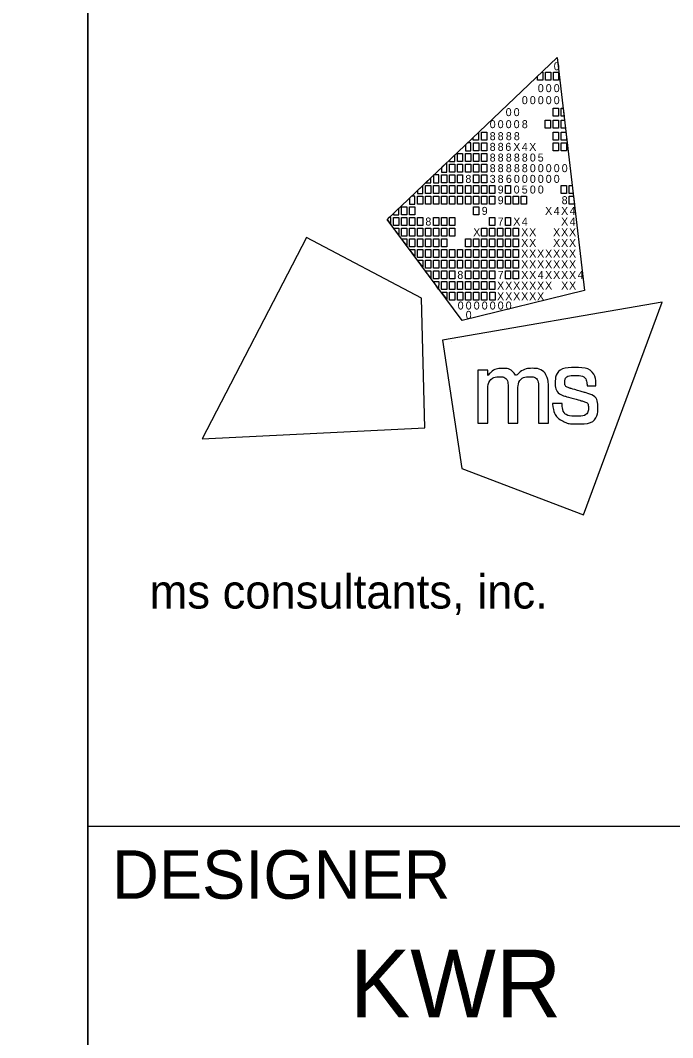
# Model space of a CAD drawing. Extents: x -0.2 to 34, y 0 to 22.
# Drawn here: x 31.86 to 33.207, y 2.063 to 4.163 of the extents above; entities that cross this region are included whole.
import ezdxf

# ---------------------------------------------------------------- set-up
doc = ezdxf.new("R2010")
doc.units = 0
for name, color, linetype in [('PV_P_Parking_Lot', 7, 'Continuous'), ('SH_Border', 7, 'Continuous'), ('SH_Data', 7, 'Continuous')]:
    doc.layers.add(name, color=color, linetype=linetype)

msp = doc.modelspace()

# ---------------------------------------------------------------- linework, layer by layer
at = {"layer": 'PV_P_Parking_Lot'}
msp.add_lwpolyline([(1.5, 21.5), (32, 21.5), (32, 0.5), (1.5, 0.5)], close=True, dxfattribs=at)
at = {"layer": 'SH_Border'}
for p, q in [((32, 0.5), (32, 21.5)), ((32, 2.5), (33.5, 2.5))]:
    msp.add_line(p, q, dxfattribs=at)
at = {"layer": 'SH_Data'}
for p, q in [((32.6175, 3.7519), (32.9688, 4.0861)), ((32.9688, 4.0861), (32.9688, 4.0861)), ((32.9688, 4.0861), (33.0253, 3.6052)), ((32.773, 3.543), (32.6175, 3.7519)), ((33.0253, 3.6052), (32.773, 3.543)), ((32.75, 3.5), (32.75, 3.5))]:
    msp.add_line(p, q, dxfattribs=at)
for points in [[(32.9279, 4.0472), (32.9369, 4.0558), (32.9389, 4.0558), (32.9389, 4.0393), (32.9279, 4.0393)], [(32.9444, 4.0558), (32.9554, 4.0558), (32.9554, 4.0393), (32.9444, 4.0393)], [(32.9609, 4.0558), (32.9719, 4.0558), (32.9719, 4.0393), (32.9609, 4.0393)], [(32.9606, 3.9815), (32.9716, 3.9815), (32.9716, 3.965), (32.9606, 3.965)], [(32.9771, 3.9815), (32.9811, 3.9815), (32.983, 3.965), (32.9771, 3.965)], [(32.9441, 3.9567), (32.9551, 3.9567), (32.9551, 3.9402), (32.9441, 3.9402)], [(32.9606, 3.9567), (32.9716, 3.9567), (32.9716, 3.9402), (32.9606, 3.9402)], [(32.9771, 3.9567), (32.984, 3.9567), (32.9859, 3.9402), (32.9771, 3.9402)], [(32.7953, 3.9211), (32.8064, 3.9316), (32.8064, 3.9154), (32.7953, 3.9154)], [(32.8123, 3.9319), (32.8233, 3.9319), (32.8233, 3.9154), (32.8123, 3.9154)], [(32.9606, 3.9319), (32.9716, 3.9319), (32.9716, 3.9154), (32.9606, 3.9154)], [(32.9771, 3.9319), (32.9869, 3.9319), (32.9881, 3.9218), (32.9881, 3.9154), (32.9771, 3.9154)], [(32.7958, 3.9099), (32.8068, 3.9099), (32.8068, 3.8934), (32.7958, 3.8934)], [(32.8123, 3.9099), (32.8233, 3.9099), (32.8233, 3.8934), (32.8123, 3.8934)], [(32.9606, 3.9099), (32.9716, 3.9099), (32.9716, 3.8934), (32.9606, 3.8934)], [(32.9771, 3.9099), (32.9881, 3.9099), (32.9881, 3.8934), (32.9771, 3.8934)], [(32.7627, 3.8879), (32.7737, 3.8879), (32.7737, 3.8714), (32.7627, 3.8714)], [(32.7793, 3.8879), (32.7903, 3.8879), (32.7903, 3.8714), (32.7793, 3.8714)], [(32.7958, 3.8879), (32.8068, 3.8879), (32.8068, 3.8714), (32.7958, 3.8714)], [(32.8123, 3.8879), (32.8233, 3.8879), (32.8233, 3.8714), (32.8123, 3.8714)], [(32.7462, 3.8659), (32.7572, 3.8659), (32.7572, 3.8494), (32.7462, 3.8494)], [(32.7627, 3.8659), (32.7737, 3.8659), (32.7737, 3.8494), (32.7627, 3.8494)], [(32.7793, 3.8659), (32.7903, 3.8659), (32.7903, 3.8494), (32.7793, 3.8494)], [(32.7958, 3.8659), (32.8068, 3.8659), (32.8068, 3.8494), (32.7958, 3.8494)], [(32.8123, 3.8659), (32.8233, 3.8659), (32.8233, 3.8494), (32.8123, 3.8494)], [(32.7297, 3.8439), (32.7407, 3.8439), (32.7407, 3.8273), (32.7297, 3.8273)], [(32.7462, 3.8439), (32.7572, 3.8439), (32.7572, 3.8273), (32.7462, 3.8273)], [(32.7627, 3.8439), (32.7737, 3.8439), (32.7737, 3.8273), (32.7627, 3.8273)], [(32.7958, 3.8439), (32.8068, 3.8439), (32.8068, 3.8273), (32.7958, 3.8273)], [(32.8123, 3.8439), (32.8233, 3.8439), (32.8233, 3.8273), (32.8123, 3.8273)], [(32.6967, 3.8218), (32.7077, 3.8218), (32.7077, 3.8053), (32.6967, 3.8053)], [(32.7132, 3.8218), (32.7242, 3.8218), (32.7242, 3.8053), (32.7132, 3.8053)], [(32.7297, 3.8218), (32.7407, 3.8218), (32.7407, 3.8053), (32.7297, 3.8053)], [(32.7462, 3.8218), (32.7572, 3.8218), (32.7572, 3.8053), (32.7462, 3.8053)], [(32.7627, 3.8218), (32.7737, 3.8218), (32.7737, 3.8053), (32.7627, 3.8053)], [(32.7793, 3.8218), (32.7903, 3.8218), (32.7903, 3.8053), (32.7793, 3.8053)], [(32.7958, 3.8218), (32.8068, 3.8218), (32.8068, 3.8053), (32.7958, 3.8053)], [(32.8123, 3.8218), (32.8233, 3.8218), (32.8233, 3.8053), (32.8123, 3.8053)], [(32.8288, 3.8218), (32.8398, 3.8218), (32.8398, 3.8053), (32.8288, 3.8053)], [(32.8618, 3.8218), (32.8728, 3.8218), (32.8728, 3.8053), (32.8618, 3.8053)], [(32.9771, 3.8218), (32.9881, 3.8218), (32.9881, 3.8053), (32.9771, 3.8053)], [(32.9935, 3.8218), (32.9998, 3.8218), (33.0018, 3.8053), (32.9935, 3.8053)], [(32.6802, 3.7998), (32.6912, 3.7998), (32.6912, 3.7833), (32.6802, 3.7833)], [(32.6967, 3.7998), (32.7077, 3.7998), (32.7077, 3.7833), (32.6967, 3.7833)], [(32.7132, 3.7998), (32.7242, 3.7998), (32.7242, 3.7833), (32.7132, 3.7833)], [(32.7297, 3.7998), (32.7407, 3.7998), (32.7407, 3.7833), (32.7297, 3.7833)], [(32.7462, 3.7998), (32.7572, 3.7998), (32.7572, 3.7833), (32.7462, 3.7833)], [(32.7627, 3.7998), (32.7737, 3.7998), (32.7737, 3.7833), (32.7627, 3.7833)], [(32.7793, 3.7998), (32.7903, 3.7998), (32.7903, 3.7833), (32.7793, 3.7833)], [(32.7958, 3.7998), (32.8068, 3.7998), (32.8068, 3.7833), (32.7958, 3.7833)], [(32.8123, 3.7998), (32.8233, 3.7998), (32.8233, 3.7833), (32.8123, 3.7833)], [(32.8288, 3.7998), (32.8398, 3.7998), (32.8398, 3.7833), (32.8288, 3.7833)], [(32.8618, 3.7998), (32.8728, 3.7998), (32.8728, 3.7833), (32.8618, 3.7833)], [(32.8783, 3.7998), (32.8893, 3.7998), (32.8893, 3.7833), (32.8783, 3.7833)], [(32.8947, 3.7998), (32.9057, 3.7998), (32.9057, 3.7833), (32.8947, 3.7833)], [(32.9935, 3.7998), (33.0024, 3.7998), (33.0044, 3.7833), (32.9935, 3.7833)], [(32.6471, 3.7778), (32.6581, 3.7778), (32.6581, 3.7613), (32.6471, 3.7613)], [(32.6637, 3.7778), (32.6747, 3.7778), (32.6747, 3.7613), (32.6637, 3.7613)], [(32.7958, 3.7778), (32.8068, 3.7778), (32.8068, 3.7613), (32.7958, 3.7613)], [(32.6306, 3.7558), (32.6416, 3.7558), (32.6416, 3.7393), (32.6306, 3.7393)], [(32.6471, 3.7558), (32.6581, 3.7558), (32.6581, 3.7393), (32.6471, 3.7393)], [(32.6637, 3.7558), (32.6747, 3.7558), (32.6747, 3.7393), (32.6637, 3.7393)], [(32.6802, 3.7558), (32.6912, 3.7558), (32.6912, 3.7393), (32.6802, 3.7393)], [(32.7132, 3.7558), (32.7242, 3.7558), (32.7242, 3.7393), (32.7132, 3.7393)], [(32.7297, 3.7558), (32.7407, 3.7558), (32.7407, 3.7393), (32.7297, 3.7393)], [(32.7462, 3.7558), (32.7572, 3.7558), (32.7572, 3.7393), (32.7462, 3.7393)], [(32.8288, 3.7558), (32.8398, 3.7558), (32.8398, 3.7393), (32.8288, 3.7393)], [(32.8618, 3.7558), (32.8728, 3.7558), (32.8728, 3.7393), (32.8618, 3.7393)], [(32.6306, 3.7338), (32.6416, 3.7338), (32.6416, 3.72)], [(32.6471, 3.7338), (32.6581, 3.7338), (32.6581, 3.7173), (32.6471, 3.7173)], [(32.6637, 3.7338), (32.6747, 3.7338), (32.6747, 3.7173), (32.6637, 3.7173)], [(32.6802, 3.7338), (32.6912, 3.7338), (32.6912, 3.7173), (32.6802, 3.7173)], [(32.6967, 3.7338), (32.7077, 3.7338), (32.7077, 3.7173), (32.6967, 3.7173)], [(32.7132, 3.7338), (32.7242, 3.7338), (32.7242, 3.7173), (32.7132, 3.7173)], [(32.7297, 3.7338), (32.7407, 3.7338), (32.7407, 3.7173), (32.7297, 3.7173)], [(32.7462, 3.7338), (32.7572, 3.7338), (32.7572, 3.7173), (32.7462, 3.7173)], [(32.8123, 3.7338), (32.8233, 3.7338), (32.8233, 3.7173), (32.8123, 3.7173)], [(32.8288, 3.7338), (32.8398, 3.7338), (32.8398, 3.7173), (32.8288, 3.7173)], [(32.8453, 3.7338), (32.8563, 3.7338), (32.8563, 3.7173), (32.8453, 3.7173)], [(32.8618, 3.7338), (32.8728, 3.7338), (32.8728, 3.7173), (32.8618, 3.7173)], [(32.8783, 3.7338), (32.8893, 3.7338), (32.8893, 3.7173), (32.8783, 3.7173)], [(32.6471, 3.7117), (32.6581, 3.7117), (32.6581, 3.698)], [(32.6637, 3.7117), (32.6747, 3.7117), (32.6747, 3.6952), (32.6637, 3.6952)], [(32.6802, 3.7117), (32.6912, 3.7117), (32.6912, 3.6952), (32.6802, 3.6952)], [(32.6967, 3.7117), (32.7077, 3.7117), (32.7077, 3.6952), (32.6967, 3.6952)], [(32.7132, 3.7117), (32.7242, 3.7117), (32.7242, 3.6952), (32.7132, 3.6952)], [(32.7297, 3.7117), (32.7407, 3.7117), (32.7407, 3.6952), (32.7297, 3.6952)], [(32.7793, 3.7117), (32.7903, 3.7117), (32.7903, 3.6952), (32.7793, 3.6952)], [(32.7958, 3.7117), (32.8068, 3.7117), (32.8068, 3.6952), (32.7958, 3.6952)], [(32.8123, 3.7117), (32.8233, 3.7117), (32.8233, 3.6952), (32.8123, 3.6952)], [(32.8288, 3.7117), (32.8398, 3.7117), (32.8398, 3.6952), (32.8288, 3.6952)], [(32.8453, 3.7117), (32.8563, 3.7117), (32.8563, 3.6952), (32.8453, 3.6952)], [(32.8618, 3.7117), (32.8728, 3.7117), (32.8728, 3.6952), (32.8618, 3.6952)], [(32.8783, 3.7117), (32.8893, 3.7117), (32.8893, 3.6952), (32.8783, 3.6952)], [(32.6637, 3.6897), (32.6747, 3.6897), (32.6747, 3.676)], [(32.6747, 3.6897), (32.6747, 3.6897), (32.6747, 3.6897)], [(32.6802, 3.6897), (32.6912, 3.6897), (32.6912, 3.6732), (32.6802, 3.6732)], [(32.6967, 3.6897), (32.7077, 3.6897), (32.7077, 3.6732), (32.6967, 3.6732)], [(32.7132, 3.6897), (32.7242, 3.6897), (32.7242, 3.6732), (32.7132, 3.6732)], [(32.7297, 3.6897), (32.7407, 3.6897), (32.7407, 3.6732), (32.7297, 3.6732)], [(32.7462, 3.6897), (32.7572, 3.6897), (32.7572, 3.6732), (32.7462, 3.6732)], [(32.7627, 3.6897), (32.7737, 3.6897), (32.7737, 3.6732), (32.7627, 3.6732)], [(32.7793, 3.6897), (32.7903, 3.6897), (32.7903, 3.6732), (32.7793, 3.6732)], [(32.7958, 3.6897), (32.8068, 3.6897), (32.8068, 3.6732), (32.7958, 3.6732)], [(32.8123, 3.6897), (32.8233, 3.6897), (32.8233, 3.6732), (32.8123, 3.6732)], [(32.8288, 3.6897), (32.8398, 3.6897), (32.8398, 3.6732), (32.8288, 3.6732)], [(32.8453, 3.6897), (32.8563, 3.6897), (32.8563, 3.6732), (32.8453, 3.6732)], [(32.8618, 3.6897), (32.8728, 3.6897), (32.8728, 3.6732), (32.8618, 3.6732)], [(32.8783, 3.6897), (32.8893, 3.6897), (32.8893, 3.6732), (32.8783, 3.6732)], [(32.6802, 3.6677), (32.6912, 3.6677), (32.6912, 3.654)], [(32.6967, 3.6677), (32.7077, 3.6677), (32.7077, 3.6512), (32.6967, 3.6512)], [(32.7132, 3.6677), (32.7242, 3.6677), (32.7242, 3.6512), (32.7132, 3.6512)], [(32.7297, 3.6677), (32.7407, 3.6677), (32.7407, 3.6512), (32.7297, 3.6512)], [(32.7462, 3.6677), (32.7572, 3.6677), (32.7572, 3.6512), (32.7462, 3.6512)], [(32.7627, 3.6677), (32.7737, 3.6677), (32.7737, 3.6512), (32.7627, 3.6512)], [(32.7793, 3.6677), (32.7903, 3.6677), (32.7903, 3.6512), (32.7793, 3.6512)], [(32.7958, 3.6677), (32.8068, 3.6677), (32.8068, 3.6512), (32.7958, 3.6512)], [(32.8123, 3.6677), (32.8233, 3.6677), (32.8233, 3.6512), (32.8123, 3.6512)], [(32.8288, 3.6677), (32.8398, 3.6677), (32.8398, 3.6512), (32.8288, 3.6512)], [(32.8453, 3.6677), (32.8563, 3.6677), (32.8563, 3.6512), (32.8453, 3.6512)], [(32.8618, 3.6677), (32.8728, 3.6677), (32.8728, 3.6512), (32.8618, 3.6512)], [(32.8783, 3.6677), (32.8893, 3.6677), (32.8893, 3.6512), (32.8783, 3.6512)], [(32.7077, 3.6305), (32.6965, 3.6457), (32.7077, 3.6457)], [(32.7132, 3.6457), (32.7242, 3.6457), (32.7242, 3.6292), (32.7132, 3.6292)], [(32.7297, 3.6457), (32.7407, 3.6457), (32.7407, 3.6292), (32.7297, 3.6292)], [(32.7462, 3.6457), (32.7572, 3.6457), (32.7572, 3.6292), (32.7462, 3.6292)], [(32.7793, 3.6457), (32.7903, 3.6457), (32.7903, 3.6292), (32.7793, 3.6292)], [(32.7958, 3.6457), (32.8068, 3.6457), (32.8068, 3.6292), (32.7958, 3.6292)], [(32.8123, 3.6457), (32.8233, 3.6457), (32.8233, 3.6292), (32.8123, 3.6292)], [(32.8288, 3.6457), (32.8398, 3.6457), (32.8398, 3.6292), (32.8288, 3.6292)], [(32.8618, 3.6457), (32.8728, 3.6457), (32.8728, 3.6292), (32.8618, 3.6292)], [(32.8783, 3.6457), (32.8893, 3.6457), (32.8893, 3.6292), (32.8783, 3.6292)], [(32.724, 3.6082), (32.7132, 3.6237), (32.7242, 3.6237)], [(32.7297, 3.6237), (32.7407, 3.6237), (32.7407, 3.6072), (32.7297, 3.6072)], [(32.7462, 3.6237), (32.7572, 3.6237), (32.7572, 3.6072), (32.7462, 3.6072)], [(32.7627, 3.6237), (32.7737, 3.6237), (32.7737, 3.6072), (32.7627, 3.6072)], [(32.7793, 3.6237), (32.7903, 3.6237), (32.7903, 3.6072), (32.7793, 3.6072)], [(32.7958, 3.6237), (32.8068, 3.6237), (32.8068, 3.6072), (32.7958, 3.6072)], [(32.8123, 3.6237), (32.8233, 3.6237), (32.8233, 3.6072), (32.8123, 3.6072)], [(32.8288, 3.6237), (32.8398, 3.6237), (32.8398, 3.6072), (32.8288, 3.6072)], [(32.7302, 3.6017), (32.7407, 3.6017), (32.7408, 3.5875)], [(32.7463, 3.6017), (32.7573, 3.6017), (32.7573, 3.5852), (32.7463, 3.5852)], [(32.763, 3.6017), (32.774, 3.6017), (32.774, 3.5852), (32.763, 3.5852)], [(32.7794, 3.6017), (32.7904, 3.6017), (32.7904, 3.5852), (32.7794, 3.5852)], [(32.796, 3.6017), (32.807, 3.6017), (32.807, 3.5852), (32.796, 3.5852)], [(32.8129, 3.6017), (32.8239, 3.6017), (32.8239, 3.5851), (32.8129, 3.5851)], [(32.8296, 3.6017), (32.8406, 3.6017), (32.8406, 3.5851), (32.8296, 3.5851)]]:
    msp.add_lwpolyline(points, close=True, dxfattribs=at)
for points in [[(32.7903, 3.9099), (32.7836, 3.9099), (32.7793, 3.9058), (32.7793, 3.8934), (32.7903, 3.8934), (32.7903, 3.9099)], [(32.7572, 3.8849), (32.7462, 3.8744), (32.7462, 3.8714), (32.7572, 3.8714), (32.7572, 3.8849)], [(32.7407, 3.8691), (32.7297, 3.8587), (32.7297, 3.8494), (32.7407, 3.8494), (32.7407, 3.8691)], [(32.7242, 3.8439), (32.7141, 3.8439), (32.7132, 3.843), (32.7132, 3.8273), (32.7242, 3.8273), (32.7242, 3.8439)], [(32.6912, 3.822), (32.6802, 3.8115), (32.6802, 3.8053), (32.6912, 3.8053), (32.6912, 3.822)], [(32.7077, 3.8377), (32.6968, 3.8273), (32.7077, 3.8273), (32.7077, 3.8377)], [(32.6747, 3.7998), (32.6679, 3.7998), (32.6637, 3.7958), (32.6637, 3.7833), (32.6747, 3.7833), (32.6747, 3.7998)], [(32.6416, 3.7749), (32.6306, 3.7644), (32.6306, 3.7613), (32.6416, 3.7613), (32.6416, 3.7749)], [(32.6251, 3.7558), (32.6216, 3.7558), (32.6175, 3.7519), (32.6251, 3.7417), (32.6251, 3.7558)], [(32.4512, 3.7149), (32.2359, 3.2988), (32.6956, 3.3215), (32.6884, 3.5892), (32.4512, 3.7149)], [(33.0229, 3.1422), (33.1859, 3.5814), (32.7324, 3.5029), (32.7722, 3.2381), (33.0229, 3.1422)]]:
    msp.add_lwpolyline(points, dxfattribs=at)
for points in [[(32.8048, 3.3315), (32.8048, 3.3315), (32.8048, 3.4409), (32.8048, 3.4409), (32.8048, 3.4409), (32.8255, 3.4409), (32.8255, 3.4409), (32.8255, 3.4409), (32.8255, 3.4297), (32.8255, 3.4297), (32.8346, 3.4399), (32.8457, 3.4445), (32.8555, 3.4445), (32.8688, 3.4445), (32.8791, 3.4372), (32.8837, 3.4266), (32.8915, 3.4381), (32.905, 3.4446), (32.9166, 3.4446), (32.9325, 3.4446), (32.9451, 3.435), (32.9494, 3.4213), (32.9494, 3.4212), (32.9494, 3.4212), (32.9494, 3.4212), (32.9501, 3.419), (32.9506, 3.4172), (32.9506, 3.4071), (32.9506, 3.4071), (32.9506, 3.3314), (32.9506, 3.3314), (32.9506, 3.3314), (32.9303, 3.3314), (32.9303, 3.3314), (32.9303, 3.3314), (32.9303, 3.4048), (32.9303, 3.4048), (32.9303, 3.4201), (32.9219, 3.4274), (32.911, 3.4274), (32.8995, 3.4274), (32.8879, 3.4171), (32.8879, 3.4001), (32.8879, 3.4001), (32.8879, 3.3315), (32.8879, 3.3315), (32.8879, 3.3315), (32.8674, 3.3315), (32.8674, 3.3315), (32.8674, 3.3315), (32.8674, 3.4059), (32.8674, 3.4059), (32.8674, 3.4203), (32.8588, 3.4274), (32.8496, 3.4274), (32.8384, 3.4274), (32.8254, 3.417), (32.8254, 3.3962), (32.8254, 3.3962), (32.8254, 3.3315), (32.8254, 3.3315), (32.8254, 3.3315), (32.8048, 3.3315), (32.8048, 3.3315)], [(32.9595, 3.3709), (32.9595, 3.3709), (32.9595, 3.3717), (32.9595, 3.3717), (32.9595, 3.3717), (32.9603, 3.3717), (32.9603, 3.3717), (32.9603, 3.3717), (32.9783, 3.3717), (32.9783, 3.3717), (32.9783, 3.3717), (32.9789, 3.3717), (32.9789, 3.3717), (32.9789, 3.3717), (32.979, 3.371), (32.979, 3.371), (32.9803, 3.3554), (32.9887, 3.346), (33.009, 3.346), (33.0273, 3.346), (33.0333, 3.3554), (33.0333, 3.3631), (33.0333, 3.3732), (33.0256, 3.3758), (33.0175, 3.378), (33.0175, 3.378), (32.987, 3.3867), (32.987, 3.3867), (32.972, 3.3909), (32.9648, 3.4019), (32.9648, 3.4142), (32.9648, 3.4303), (32.9768, 3.4462), (33.0052, 3.4462), (33.0348, 3.4462), (33.0489, 3.4285), (33.0489, 3.4095), (33.0489, 3.4095), (33.0489, 3.4087), (33.0489, 3.4087), (33.0489, 3.4087), (33.0482, 3.4087), (33.0482, 3.4087), (33.0482, 3.4087), (33.0312, 3.4087), (33.0312, 3.4087), (33.0312, 3.4087), (33.0305, 3.4087), (33.0305, 3.4087), (33.0305, 3.4087), (33.0305, 3.4094), (33.0305, 3.4094), (33.0301, 3.4208), (33.0226, 3.43), (33.0056, 3.43), (32.9891, 3.43), (32.9843, 3.4218), (32.9843, 3.4157), (32.9843, 3.4108), (32.9869, 3.4059), (32.9959, 3.4033), (32.9959, 3.4033), (33.0255, 3.3948), (33.0255, 3.3948), (33.0462, 3.3889), (33.0527, 3.3777), (33.0527, 3.3639), (33.0527, 3.3462), (33.041, 3.3298), (33.0087, 3.3298), (32.9952, 3.3298), (32.9877, 3.3321), (32.9823, 3.3348), (32.969, 3.3414), (32.9609, 3.3536), (32.9595, 3.3709)]]:
    msp.add_open_spline(points, degree=3, dxfattribs=at)

# ---------------------------------------------------------------- texts
for s, height, p in [('0', 0.0165, (32.9617, 4.0597)), ('0', 0.0165, (32.9288, 4.0145)), ('0', 0.0165, (32.9452, 4.0145)), ('0', 0.0165, (32.9617, 4.0145)), ('0', 0.0165, (32.8958, 3.9897)), ('0', 0.0165, (32.9123, 3.9897)), ('0', 0.0165, (32.9288, 3.9897)), ('0', 0.0165, (32.9452, 3.9897)), ('0', 0.0165, (32.9617, 3.9897)), ('0', 0.0165, (32.8625, 3.965)), ('0', 0.0165, (32.879, 3.965)), ('0', 0.0165, (32.8295, 3.9402)), ('0', 0.0165, (32.846, 3.9402)), ('0', 0.0165, (32.8625, 3.9402)), ('0', 0.0165, (32.879, 3.9402)), ('8', 0.0165, (32.8958, 3.9402)), ('8', 0.0165, (32.8295, 3.9154)), ('8', 0.0165, (32.846, 3.9154)), ('8', 0.0165, (32.8628, 3.9154)), ('8', 0.0165, (32.8793, 3.9154)), ('8', 0.0165, (32.8295, 3.8934)), ('8', 0.0165, (32.846, 3.8934)), ('6', 0.0165, (32.8618, 3.8934)), ('X', 0.0165, (32.8781, 3.8934)), ('4', 0.0165, (32.8958, 3.8934)), ('X', 0.0165, (32.911, 3.8934)), ('8', 0.0165, (32.8295, 3.8713)), ('8', 0.0165, (32.846, 3.8713)), ('8', 0.0165, (32.8628, 3.8713)), ('8', 0.0165, (32.8794, 3.8713)), ('8', 0.0165, (32.8958, 3.8713)), ('0', 0.0165, (32.9123, 3.8713)), ('5', 0.0165, (32.9287, 3.8713)), ('8', 0.0165, (32.8295, 3.8494)), ('8', 0.0165, (32.846, 3.8494)), ('8', 0.0165, (32.8628, 3.8494)), ('8', 0.0165, (32.8794, 3.8494)), ('8', 0.0165, (32.8958, 3.8494)), ('0', 0.0165, (32.9123, 3.8494)), ('0', 0.0165, (32.9288, 3.8494)), ('0', 0.0165, (32.9452, 3.8494)), ('0', 0.0165, (32.9617, 3.8494)), ('0', 0.0165, (32.9782, 3.8494)), ('8', 0.0165, (32.7793, 3.8273)), ('3', 0.0165, (32.8295, 3.8273)), ('8', 0.0165, (32.846, 3.8273)), ('6', 0.0165, (32.8629, 3.8273)), ('0', 0.0165, (32.8793, 3.8273)), ('0', 0.0165, (32.8958, 3.8273)), ('0', 0.0165, (32.9123, 3.8273)), ('0', 0.0165, (32.9288, 3.8273)), ('0', 0.0165, (32.9452, 3.8273)), ('0', 0.0165, (32.9617, 3.8273)), ('9', 0.0165, (32.846, 3.8053)), ('0', 0.0165, (32.879, 3.8053)), ('5', 0.0165, (32.8957, 3.8053)), ('0', 0.0165, (32.9123, 3.8053)), ('0', 0.0165, (32.9288, 3.8053)), ('9', 0.0165, (32.846, 3.7833)), ('8', 0.0165, (32.9781, 3.7833)), ('9', 0.0165, (32.813, 3.7613)), ('X', 0.0165, (32.9439, 3.7613)), ('4', 0.0165, (32.9617, 3.7613)), ('X', 0.0165, (32.9769, 3.7613)), ('4', 0.0165, (32.9946, 3.7613)), ('8', 0.0165, (32.6967, 3.7393)), ('7', 0.0165, (32.846, 3.7393)), ('X', 0.0165, (32.8781, 3.7393)), ('4', 0.0165, (32.8958, 3.7393)), ('X', 0.0165, (32.9769, 3.7393)), ('4', 0.0165, (32.9946, 3.7393)), ('X', 0.0165, (32.7955, 3.7173)), ('X', 0.0165, (32.8945, 3.7173)), ('X', 0.0165, (32.911, 3.7173)), ('X', 0.0165, (32.9604, 3.7173)), ('X', 0.0165, (32.9769, 3.7173)), ('X', 0.0165, (32.9933, 3.7173)), ('X', 0.0165, (32.8945, 3.6952)), ('X', 0.0165, (32.911, 3.6952)), ('X', 0.0165, (32.9604, 3.6952)), ('X', 0.0165, (32.9769, 3.6952)), ('X', 0.0165, (32.9933, 3.6952)), ('X', 0.0165, (32.8945, 3.6732)), ('X', 0.0165, (32.911, 3.6732)), ('X', 0.0165, (32.9274, 3.6732)), ('X', 0.0165, (32.9439, 3.6732)), ('X', 0.0165, (32.9604, 3.6732)), ('X', 0.0165, (32.9769, 3.6732)), ('X', 0.0165, (32.9933, 3.6732)), ('X', 0.0165, (32.8945, 3.6512)), ('X', 0.0165, (32.911, 3.6512)), ('X', 0.0165, (32.9274, 3.6512)), ('X', 0.0165, (32.9439, 3.6512)), ('X', 0.0165, (32.9604, 3.6512)), ('X', 0.0165, (32.9769, 3.6512)), ('X', 0.0165, (32.9933, 3.6512)), ('8', 0.0165, (32.7627, 3.6292)), ('7', 0.0165, (32.846, 3.6292)), ('X', 0.0165, (32.8945, 3.6292)), ('X', 0.0165, (32.911, 3.6292)), ('4', 0.0165, (32.9288, 3.6292)), ('X', 0.0165, (32.9439, 3.6292)), ('X', 0.0165, (32.9604, 3.6292)), ('X', 0.0165, (32.9769, 3.6292)), ('X', 0.0165, (32.9933, 3.6292)), ('4', 0.0165, (33.0111, 3.6292)), ('X', 0.0165, (32.8447, 3.6072)), ('X', 0.0165, (32.8616, 3.6072)), ('X', 0.0165, (32.878, 3.6072)), ('X', 0.0165, (32.8945, 3.6072)), ('X', 0.0165, (32.911, 3.6072)), ('X', 0.0165, (32.9274, 3.6072)), ('X', 0.0165, (32.9439, 3.6072)), ('X', 0.0165, (32.9771, 3.6072)), ('X', 0.0165, (32.9933, 3.6072)), ('X', 0.0165, (32.8447, 3.5851)), ('X', 0.0165, (32.8616, 3.5851)), ('X', 0.0165, (32.878, 3.5851)), ('X', 0.0165, (32.8945, 3.5851)), ('X', 0.0165, (32.911, 3.5851)), ('X', 0.0165, (32.9274, 3.5851)), ('0', 0.0165, (32.7634, 3.5659)), ('0', 0.0165, (32.7799, 3.5659)), ('0', 0.0165, (32.7965, 3.5659)), ('0', 0.0165, (32.813, 3.5659)), ('0', 0.0165, (32.8295, 3.5659)), ('0', 0.0165, (32.846, 3.5659)), ('0', 0.0165, (32.8625, 3.5659)), ('0', 0.0165, (32.7799, 3.5467)), ('ms consultants, inc.', 0.07, (32.1273, 2.9489))]:
    msp.add_text(s, height=height, rotation=360, dxfattribs=at).set_placement(p)
for s, height, p in [('DESIGNER', 0.1, (32.05, 2.35)), ('KWR', 0.14, (32.5407, 2.105))]:
    msp.add_text(s, height=height, dxfattribs=at).set_placement(p)

doc.saveas('drawing.dxf')
